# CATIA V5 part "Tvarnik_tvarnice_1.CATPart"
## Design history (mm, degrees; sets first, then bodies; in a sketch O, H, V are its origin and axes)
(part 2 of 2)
Body4 "Tvarnice"
  Sketch42 on face of Solid1, origin (1.6, 0, 0), H (0, 1, 0), V (0, 0, 1)
    line L1 (80, 80) -> (80, -80)
    line L2 (80, -80) -> (-80, -80)
    line L3 (-80, -80) -> (-80, 80)
    line L4 (-80, 80) -> (80, 80)
    length L4 = 160
    length L1 = 160
    vertical: L1 V, L3 V
    horizontal: L2 H, L4 H
    equidistance: L1 L3 O, L2 L4 O
  Pocket14: profile Sketch42, direction (-1, 0, 0), length 16
  Body5 "Vicko"
    Solid2: linked copy from another document
  Remove2: tool Body5
  Trim1: faces to keep start face of Pocket14, faces to remove start face of Pocket14 (x35)
  Sketch43 on start face of Pocket14, origin (1.6, 0, 0), H (0, 1, 0), V (0, 0, 1)
    projected circle E1 centre (26.45, -66.45) radius 5.1 from start face of Pocket14
    projected circle E2 centre (-26.2, -66.08) radius 5.1 from start face of Pocket14
    projected circle E3 centre (-68.2522, 13.0002) radius 5.1 from start face of Pocket14
    projected circle E4 centre (-35.5625, 59.6882) radius 5.1 from start face of Pocket14
    projected circle E5 centre (38.2049, 58.0324) radius 5.1 from start face of Pocket14
    projected circle E6 centre (70.2785, -7.2128) radius 5.1 from start face of Pocket14
  Pad6: profile Sketch43, direction (-1, 0, 0), length 3
  Sketch44 on end face of Pad6, origin (-1.4, 0, 0), H (0, 1, 0), V (0, 0, 1)
    projected circle E1 centre (70.2785, -7.2128) radius 3 from end face of Pad6
    projected circle E2 centre (38.2049, 58.0324) radius 3 from end face of Pad6
    projected circle E4 centre (-68.2522, 13.0002) radius 3 from edge [face of Solid2 | end face of Pad6]
    projected circle E5 centre (-26.2, -66.08) radius 3 from end face of Pad6
    projected circle E6 centre (26.45, -66.45) radius 3 from end face of Pad6
  Pad7: profile Sketch44, direction (-1, 0, 0), length 0.3
  Sketch45 on start face of Pocket14, origin (1.6, 0, 0), H (0, 1, 0), V (0, 0, 1)
    projected arc E1 centre (-39.7026, -63.67) radius 8 from (-33.5229, -68.7505) to (-31.75, -64.54) ccw from edge [face of Solid1 | face of Solid1]
    projected arc E3 centre (-38.7, -63.15) radius 7 from (-37.0577, -56.3454) to (-42.5892, -57.3299) ccw from edge [face of Solid1 | face of Solid1]
    projected arc E4 centre (-42.6448, -57.2467) radius 0.1 from (-42.6019, -57.337) to (-42.5892, -57.3299) ccw from edge [face of Solid1 | face of Solid1]
    projected line E5 (-42.9183, -57.4874) -> (-42.6019, -57.337) from edge [face of Solid1 | face of Solid1]
    projected arc E6 centre (-43.1328, -57.0357) radius 0.5 from (-43.5459, -57.3175) to (-42.9183, -57.4874) ccw from edge [face of Solid1 | face of Solid1]
    projected line E7 (-44.5334, -55.87) -> (-43.5459, -57.3175) from edge [face of Solid1 | face of Solid1]
    projected arc E8 centre (-44.9464, -56.1518) radius 0.5 from (-44.5334, -55.87) to (-44.634, -55.7614) ccw from edge [face of Solid1 | face of Solid1]
    projected arc E9 centre (0, 0) radius 71.425 from (-64.1739, -31.3568) to (-44.634, -55.7614) ccw from edge [face of Solid1 | face of Solid1]
    projected arc E10 centre (0, 0) radius 71.425 from (-71.1311, 6.4726) to (-64.1739, -31.3568) ccw from edge [face of Solid1 | face of Solid1]
    projected arc E11 centre (-73.1229, 6.6538) radius 2 from (-71.1311, 6.4726) to (-71.9052, 8.2404) ccw from edge [face of Solid1 | face of Solid1]
    projected arc E12 centre (-68.2522, 13.0002) radius 6 from (-69.8997, 18.7696) to (-71.9052, 8.2404) ccw from edge [face of Solid1 | face of Solid1]
    projected arc E13 centre (-70.4489, 20.6927) radius 2 from (-69.8997, 18.7696) to (-68.5299, 20.1291) ccw from edge [face of Solid1 | face of Solid1]
    projected arc E14 centre (0, 0) radius 71.425 from (-42.3563, 57.5107) to (-68.5299, 20.1291) ccw from edge [face of Solid1 | face of Solid1]
    projected arc E15 centre (-43.5423, 59.121) radius 2 from (-42.3563, 57.5107) to (-41.5474, 59.2628) ccw from edge [face of Solid1 | face of Solid1]
    projected arc E16 centre (-35.5625, 59.6882) radius 6 from (-32.3394, 64.749) to (-41.5474, 59.2628) ccw from edge [face of Solid1 | face of Solid1]
    projected arc E17 centre (-31.265, 66.4359) radius 2 from (-32.3394, 64.749) to (-30.8799, 64.4733) ccw from edge [face of Solid1 | face of Solid1]
    projected arc E18 centre (-31.265, 66.4359) radius 2 from (-30.8799, 64.4733) to (-30.4134, 64.6263) ccw from edge [face of Solid1 | face of Solid1]
    projected arc E19 centre (0, 0) radius 71.425 from (33.2826, 63.1965) to (-30.4134, 64.6263) ccw from edge [face of Solid1 | face of Solid1]
    projected arc E20 centre (34.2145, 64.9661) radius 2 from (33.2826, 63.1965) to (34.4133, 62.976) ccw from edge [face of Solid1 | face of Solid1]
    projected arc E21 centre (34.2145, 64.9661) radius 2 from (34.4133, 62.976) to (35.2121, 63.2327) ccw from edge [face of Solid1 | face of Solid1]
    projected arc E22 centre (38.2049, 58.0324) radius 6 from (44.1647, 57.3389) to (35.2121, 63.2327) ccw from edge [face of Solid1 | face of Solid1]
    projected arc E23 centre (46.1513, 57.1077) radius 2 from (44.1647, 57.3389) to (44.1679, 56.8506) ccw from edge [face of Solid1 | face of Solid1]
    projected arc E24 centre (46.1513, 57.1077) radius 2 from (44.1679, 56.8506) to (44.8942, 55.5522) ccw from edge [face of Solid1 | face of Solid1]
    projected arc E25 centre (0, 0) radius 71.425 from (68.6438, 19.7372) to (44.8942, 55.5522) ccw from edge [face of Solid1 | face of Solid1]
    projected arc E26 centre (68.5477, 19.7095) radius 0.1 from (68.6445, 19.7346) to (68.6438, 19.7372) ccw from edge [face of Solid1 | face of Solid1]
    projected arc E27 centre (68.5476, 19.7096) radius 0.1001 from (68.6357, 19.662) to (68.6445, 19.7346) ccw from edge [face of Solid1 | face of Solid1]
    projected arc E28 centre (68.5477, 19.7095) radius 0.1 from (68.6344, 19.6597) to (68.6357, 19.662) ccw from edge [face of Solid1 | face of Solid1]
    projected line E29 (65.7164, 14.5806) -> (68.6344, 19.6597) from edge [face of Solid1 | face of Solid1]
    projected arc E30 centre (69.5316, 12.3887) radius 4.4 from (65.7164, 14.5806) to (70.8571, 8.1931) ccw from edge [face of Solid1 | face of Solid1]
    projected arc E31 centre (70.8872, 8.0978) radius 0.1 from (70.9819, 8.13) to (70.8571, 8.1931) ccw from edge [face of Solid1 | face of Solid1]
    projected arc E33 centre (69.7785, -6.9628) radius 6 from (72.2645, -12.4235) to (75.4588, -5.0305) ccw from edge [face of Solid1 | face of Solid1]
    projected line E34 (70.9819, 8.13) -> (75.4588, -5.0305) from edge [face of Solid1 | face of Solid1]
    projected arc E35 centre (72.4717, -12.8786) radius 0.5 from (72.2645, -12.4235) to (72.1405, -12.504) ccw from edge [face of Solid1 | face of Solid1]
    projected line E36 (72.1405, -12.504) -> (72.0071, -12.6219) from edge [face of Solid1 | face of Solid1]
    projected line E37 (71.6567, -12.9317) -> (72.0071, -12.6219) from edge [face of Solid1 | face of Solid1]
    projected line E38 (70.1987, -14.2207) -> (71.6567, -12.9317) from edge [face of Solid1 | face of Solid1]
    projected arc E39 centre (70.861, -14.9699) radius 1 from (70.1987, -14.2207) to (69.8826, -14.7632) ccw from edge [face of Solid1 | face of Solid1]
    projected arc E40 centre (0, 0) radius 71.425 from (34.7, -62.4295) to (69.8826, -14.7632) ccw from edge [face of Solid1 | face of Solid1]
    projected line E41 (34.7, -63.3874) -> (34.7, -62.4295) from edge [face of Solid1 | face of Solid1]
    projected line E42 (34.7, -63.3874) -> (34.6998, -63.4087) from edge [face of Solid1 | face of Solid1]
    projected arc E43 centre (34.5768, -63.4037) radius 0.123 from (34.6907, -63.4503) to (34.6998, -63.4087) ccw from edge [face of Solid1 | face of Solid1]
    projected arc E45 centre (39.6, -65.7) radius 5.4 from (34.6823, -63.4692) to (34.2, -65.7) ccw from edge [face of Solid1 | face of Solid1]
    projected line E46 (34.6907, -63.4503) -> (34.6823, -63.4692) from edge [face of Solid1 | face of Solid1]
    projected arc E47 centre (27.2, -65.7) radius 7 from (29.0596, -72.4485) to (34.2, -65.7) ccw from edge [face of Solid1 | face of Solid1]
    projected line E48 (27.2179, -73.1928) -> (29.0487, -72.4522) from edge [face of Solid1 | face of Solid1]
    projected line E49 (27.2179, -73.1928) -> (27.1999, -73.1995) from edge [face of Solid1 | face of Solid1]
    projected line E50 (27.1999, -73.1995) -> (27.1807, -73.2) from edge [face of Solid1 | face of Solid1]
    projected line E51 (26.95, -73.2) -> (27.1807, -73.2) from edge [face of Solid1 | face of Solid1]
    projected arc E52 centre (26.95, -65.95) radius 7.25 from (19.7, -65.95) to (26.95, -73.2) ccw from edge [face of Solid1 | face of Solid1]
    projected line E53 (19.7, -54.5084) -> (19.7, -65.95) from edge [face of Solid1 | face of Solid1]
    projected arc E54 centre (10.55, -54.5084) radius 9.15 from (19.7, -54.5084) to (14.5407, -46.2746) ccw from edge [face of Solid1 | face of Solid1]
    projected arc E55 centre (10.55, -54.5084) radius 9.15 from (14.5407, -46.2746) to (12.2, -45.5084) ccw from edge [face of Solid1 | face of Solid1]
    projected arc E56 centre (-1.5593, -117.2) radius 73 from (12.028, -45.4756) to (8.5876, -44.9086) ccw from edge [face of Solid1 | face of Solid1]
    projected arc E57 centre (-1.5593, -117.2) radius 73 from (12.2, -45.5084) to (12.028, -45.4756) ccw from edge [face of Solid1 | face of Solid1]
    projected arc E58 centre (-1.5593, -117.2) radius 73 from (8.5876, -44.9086) to (-13.7, -45.2166) ccw from edge [face of Solid1 | face of Solid1]
    projected arc E59 centre (-12.6167, -52.2166) radius 7.0833 from (-13.7, -45.2166) to (-14.8563, -45.4967) ccw from edge [face of Solid1 | face of Solid1]
    projected arc E60 centre (-12.6167, -52.2166) radius 7.0833 from (-14.8563, -45.4967) to (-19.7, -52.2166) ccw from edge [face of Solid1 | face of Solid1]
    projected line E61 (-19.7, -52.2166) -> (-19.7, -67.2) from edge [face of Solid1 | face of Solid1]
    projected arc E62 centre (-25.7, -67.2) radius 6 from (-25.7, -73.2) to (-19.7, -67.2) ccw from edge [face of Solid1 | face of Solid1]
    projected line E63 (-25.7, -73.2) -> (-25.725, -73.1988) from edge [face of Solid1 | face of Solid1]
    projected line E64 (-25.7279, -73.1975) -> (-25.7474, -73.1876) from edge [face of Solid1 | face of Solid1]
    point P123 (-25.7279, -73.1975)
    projected line E65 (-25.7474, -73.1876) -> (-28.2581, -71.7985) from edge [face of Solid1 | face of Solid1]
    projected line E66 (-33.494, -68.9015) -> (-28.2581, -71.7985) from edge [face of Solid1 | face of Solid1]
    projected arc E67 centre (-33.4456, -68.814) radius 0.1 from (-33.5229, -68.7505) to (-33.494, -68.9015) ccw from edge [face of Solid1 | face of Solid1]
    line L1 (29.0487, -72.4522) -> (29.0596, -72.4485)
    line L2 (-25.7279, -73.1975) -> (-25.725, -73.1988)
    point P131 (-25.7279, -73.1975)
    coincidence: P131 E64, P123 P131
  Pad8: profile Sketch45, direction (-1, 0, 0), length 0.3
  Sketch46 on end face of Pocket14, origin (-14.4, 0, 0), H (0, -1, 0), V (0, 0, 1)
    line L1 (90, 90) -> (90, -90)
    line L2 (90, -90) -> (-90, -90)
    line L3 (-90, -90) -> (-90, 90)
    line L4 (-90, 90) -> (90, 90)
    length L4 = 180
    length L1 = 180
    vertical: L1 V, L3 V
    horizontal: L2 H, L4 H
    equidistance: L1 L3 O, L2 L4 O
  Pocket15: profile Sketch46, direction (-1, 0, 0), length 30
  DatumCurve31 to DatumCurve33
  Plane3: stored without definition
  Plane4: stored without definition
  Sketch47 on xy-plane, origin (0, 0, 0), H (1, 0, 0), V (0, 1, 0)
    line L1 (-5.1, 0) -> (-5.1, 1)
    arc A1 centre (-8.8103, -0.4945) radius 4 from (-5.1, 1) to (-8.6, 3.5) ccw
    line L2 (-8.6, 3.5) -> (-8.6, 0)
    line L3 (-8.6, 0) -> (-5.1, 0)
    distance L3 H = 0
    length L1 = 1
    length L2 = 3.5
    distance L1 V = 5.1
    distance L2 V = 8.6
    radius A1 = 4
    vertical: L1 V, L2 V
    horizontal: L3 H
  Shaft1: profile Sketch47, axis Sketch47.L3, angle 360
  DatumCurve34
  DatumCurve35
  Sketch48 on end face of Pocket15, origin (-44.4, 0, 0), H (0, -1, 0), V (0, 0, 1)
    projected arc E1 centre (0, 0) radius 18.5 from (18.5, 0) to (-18.5, 0) ccw from edge of DatumCurve34
    projected arc E2 centre (0, 0) radius 18.5 from (-18.5, 0) to (18.5, 0) ccw from edge of DatumCurve35
  Pad9: profile Sketch48, direction (1, 0, 0), length 29
  DatumCurve36
  DatumCurve37
  DatumSurface32
  Sketch49 on end face of Pad9, origin (-15.4, 0, 0), H (0, -1, 0), V (0, 0, 1)
    projected arc E1 centre (0, 0) radius 8.5 from (8.5, 0) to (-8.5, 0) ccw from edge of DatumCurve36
    projected arc E2 centre (0, 0) radius 8.5 from (-8.5, 0) to (8.5, 0) ccw from edge of DatumCurve37
  Pad10: profile Sketch49, direction (1, 0, 0), length 6.8
  Sketch50 on face of Solid1, origin (-2.9, 0, 0), H (0, -1, 0), V (0, 0, 1)
    projected circle E1 centre (10, 25) radius 3.5 from edge [end face of Pad4 | face of Pocket7 from Sketch12.E8]
  Sketch51 on face of Pocket15 from Sketch46.L4, origin (0, 0, 90), H (1, 0, 0), V (0, 1, 0)
    circle A1 centre (-30.4, 65) radius 5
    point P1 (-30.4, 65)
    circle A2 centre (-30.4, 33) radius 5
    point P2 (-30.4, 33)
    circle A3 centre (-30.4, -33) radius 5
    point P3 (-30.4, -33)
    circle A4 centre (-30.4, -65) radius 5
    point P4 (-30.4, -65)
    construction line L1 (-14.4, -85) -> (-44.4, -85)
    construction line L2 (-14.4, 85) -> (-44.4, 85)
    radius A4 = 5
    radius A3 = 5
    radius A2 = 5
    radius A1 = 5
    distance P4 L1 = 20
    distance P3 P4 = 32
    distance L2 P1 = 20
    distance P2 P1 = 32
  Pad11: profile Sketch51, direction (0, 0, -1), up to the existing solid (limit type 2)
  Sketch52 on face of Pad4 from Sketch9.L4, origin (0, 0, 90), H (1, 0, 0), V (0, 1, 0)
    circle A1 centre (34.9443, -53.3819) radius 5
    circle A2 centre (34.9443, 5.4608) radius 5
    circle A3 centre (34.9443, 54.6938) radius 5
    circle A4 centre (34.9443, 77.599) radius 5
    point P4 (34.9443, 77.599)
    reference projected line E1 (47.6, 90) -> (47.6, -90) from edge [face of Pad4 from Sketch9.L4 | end face of Pad4]
    radius A4 = 5
    radius A3 = 5
    radius A2 = 5
    radius A1 = 5
    distance P4 E1 = 12.6557
  Body6 "MANIFOLD_SOLID_BREP #135"
    Solid3: solid without history
  Remove3: tool Body6
  Sketch53 on face of Solid2, origin (0, 11.5, 0), H (-1, 0, 0), V (0, 0, 1)
  Pad12: profile Sketch53, direction (0, -1, 0), up to face of Solid2
  Sketch54 on face of Solid2, origin (0, -11.5, 0), H (1, 0, 0), V (0, 0, 1)
    projected line E1 (-2.8, -44.0344) -> (-0.8933, -43.906) from edge [face of Solid2 | face of Solid2]
    point P1 (-2.8, -44.0344)
    projected arc E2 centre (-0.9006, -43.8056) radius 0.1006 from (-0.8933, -43.906) to (-0.8, -43.8052) ccw from edge [face of Solid2 | face of Solid2]
    projected line E3 (-0.8, -43.8052) -> (-0.8, -44.1794) from edge [face of Solid2 | face of Pad12]
    projected arc E4 centre (-0.9007, -44.1803) radius 0.1007 from (-0.8933, -44.2807) to (-0.8, -44.1794) ccw from edge [face of Solid2 | face of Pad12]
    projected line E5 (-0.8933, -44.2807) -> (-0.4, -44.2807) from edge [face of Solid2 | face of Pad12]
    projected line E6 (-0.4, -44.8326) -> (-0.4, -44.2807) from edge [face of Solid2 | face of Solid2]
    projected line E7 (-0.4, -44.8326) -> (-2.8, -44.7051) from edge [face of Solid2 | face of Solid2]
    line L1 (-2.8, -44.0344) -> (-3.0461, -44.0509)
    point P15 (-2.8, -44.0344)
    line L2 (-2.8, -44.7051) -> (-3.0461, -44.692)
    point P17 (-3.0461, -44.692)
    line L3 (-3.0461, -44.692) -> (-3.0461, -44.0509)
    point P18 (-3.0461, -44.692)
    length L3 = 0.6411
    distance P15 P1 = 0
    distance P17 P18 = 0
    coincidence: P15 E1, P18 L2
    tangency: L1 E2
    parallelism: L2 E7
    vertical: L3 V
  Sketch55 on start face of Pocket14, origin (1.6, 0, 0), H (0, 1, 0), V (0, 0, 1)
    projected arc E1 centre (-1.3665, -117.1471) radius 73.0211 from (-11, -44.7643) to (-11.5, -44.8326) ccw from edge [face of Solid2 | face of Solid2]
  Rib1: profile Sketch54, centre curve Sketch55
  Sketch56 on face of Solid3, origin (0, -11, 0), H (-1, 0, 0), V (0, 0, 1)
    line L1 (0.7047, -44.3237) -> (1.0185, -44.3237)
    line L2 (1.0185, -44.3237) -> (1.0185, -44.065)
    line L3 (1.0185, -44.065) -> (0.7047, -44.065)
    line L4 (0.7047, -44.065) -> (0.7047, -44.3237)
    horizontal: L1 H, L3 H
    vertical: L2 V, L4 V
  Pad13: profile Sketch56, direction (0, -1, 0), length 1
  Sketch57 on face of Solid3, origin (0, 12, 0), H (1, 0, 0), V (0, 0, 1)
    projected line E1 (-2.9, -44.5067) -> (-2.8052, -44.5003) from edge [face of Solid2 | face of Solid3]
    projected line E2 (-2.8052, -44.5003) -> (-0.8933, -44.3707) from edge [face of Solid2 | face of Solid3]
    line L1 (-2.9, -44.5067) -> (-2.9, -44.3067)
    line L2 (-2.9, -44.3067) -> (-0.8933, -44.3707)
    length L1 = 0.2
    vertical: L1 V
  Sketch58 on face of Pad12, origin (-0.8, 0, 0), H (0, 1, 0), V (0, 0, 1)
    projected arc E1 centre (-1.1745, -116.1657) radius 72.9938 from (2.4737, -43.2632) to (-1.0654, -43.172) ccw from edge [face of Solid3 | face of Pad12]
    projected arc E2 centre (-1.1745, -116.1657) radius 72.9938 from (10.9113, -44.1794) to (6.5, -43.5765) ccw from edge [face of Solid3 | face of Pad12]
    projected line E3 (11.4217, -44.267) -> (10.9113, -44.1794) from edge [face of Pad12 | face of Solid3]
    projected arc E4 centre (-0.6882, -116.2646) radius 73.0936 from (-6.5, -43.4025) to (-10.994, -43.9012) ccw from edge [face of Pad12 | face of Solid3]
    point P7 (-6.5, -43.4025)
    arc A1 centre (-0.6882, -116.2646) radius 73.0936 from (-6.5, -43.4025) to (-1.0654, -43.172) cw
    point P10 (-6.5, -43.4025)
    point P11 (-3.695, -43.2329)
    arc A2 centre (-1.1745, -116.1657) radius 72.9938 from (2.4737, -43.2632) to (6.5, -43.5765) cw
    point P13 (5.4808, -43.476)
    arc A3 centre (4.3044, -85.7576) radius 42.0967 from (11.4217, -44.267) to (12.116, -44.3921) cw
    point P15 (12.116, -44.3921)
    coincidence: P10 E4, A1 P11, P11 E4, A2 P13, P13 E2, P15 E2, P7 P10
    tangency: A3 E3
  Slot1: profile Sketch57, centre curve Sketch58
  DatumSurface33
  Sketch59 on face of Pad12, origin (-0.8, 0, 0), H (0, 1, 0), V (0, 0, 1)
    projected arc E1 centre (-1.1745, -116.1657) radius 72.9938 from (2.4737, -43.2632) to (-1.0654, -43.172) ccw from edge [face of Solid3 | face of Pad12]
    projected arc E2 centre (-0.6882, -116.2646) radius 73.0936 from (-1.0654, -43.172) to (-1.9017, -43.1811) ccw from edge [face of Pad12 | face of Solid3]
    projected arc E3 centre (-0.6882, -116.2646) radius 73.0936 from (-1.9017, -43.1811) to (-2, -43.1828) ccw from edge [face of Pad12 | face of Solid3]
    projected arc E4 centre (-0.6882, -116.2646) radius 73.0936 from (-6.5, -43.4025) to (-10.994, -43.9012) ccw from edge [face of Pad12 | face of Solid3]
    projected arc E5 centre (-1.1745, -116.1657) radius 72.9938 from (10.9113, -44.1794) to (6.5, -43.5765) ccw from edge [face of Solid3 | face of Pad12]
    arc A1 centre (-0.6882, -116.2646) radius 73.0936 from (-10.994, -43.9012) to (-11.5363, -43.9806) ccw
    point P12 (-11.5363, -43.9806)
    point P13 (-11.4271, -43.9642)
    arc A2 centre (-0.6882, -116.2646) radius 73.0936 from (-6.5, -43.4025) to (-2, -43.1828) cw
    point P15 (-6.5, -43.4025)
    point P16 (-2.4662, -43.1927)
    arc A3 centre (-1.1745, -116.1657) radius 72.9938 from (6.5, -43.5765) to (2.4737, -43.2632) ccw
    point P18 (4.2149, -43.3712)
    arc A4 centre (-1.1745, -116.1657) radius 72.9938 from (10.9113, -44.1794) to (12.2372, -44.4146) cw
    point P20 (12.2372, -44.4146)
    point P21 (12.1539, -44.3991)
    coincidence: P12 E4, A1 P13, P13 E4, P15 E4, A2 P16, P16 E3, A3 P18, P18 E5, P20 E5, A4 P21, P21 E5
  Sketch60 on face of Rib1, origin (0, -10.6901, 0.0739), H (1, 0, 0), V (0, 0.0069, 1)
    projected arc E1 centre (-0.9006, -43.8123) radius 0.1006 from (-0.8933, -43.9126) to (-0.8, -43.8118) ccw from edge [face of Rib1 | face of Rib1]
    projected line E2 (-0.8, -43.9762) -> (-0.8, -43.8118) from edge [face of Pad12 | face of Rib1]
    point P3 (-0.8, -43.9762)
    projected line E3 (-2.9, -44.0773) -> (-0.8, -43.9762) from edge [face of Solid3 | face of Rib1]
    point P6 (-0.8, -43.9762)
    projected line E4 (-2.8052, -44.099) -> (-1.1087, -43.9903) from edge [face of Slot1 | face of Slot1]
    projected line E5 (-2.9, -44.0723) -> (-2.9, -44.1051) from edge [face of Slot1 | face of Slot1]
    projected line E6 (-2.9, -44.0773) -> (-2.9, -44.0477) from edge [face of Rib1 | face of Slot1]
    projected line E7 (-2.9, -44.0723) -> (-2.9, -44.0477) from edge [face of Rib1 | face of Slot1]
    point P12 (-2.9, -44.0477)
    projected line E8 (-2.8, -44.041) -> (-2.9, -44.0477) from edge [face of Rib1 | face of Rib1]
    point P14 (-2.9, -44.0477)
    projected line E9 (-1.8374, -43.9762) -> (-2.8, -44.041) from edge [face of Rib1 | face of Rib1]
    projected line E10 (-0.8933, -43.9126) -> (-1.5388, -43.9561) from edge [face of Rib1 | face of Rib1]
    line L1 (-1.8374, -43.9762) -> (-1.5388, -43.9561)
    line L2 (-2.9, -44.1051) -> (-2.9, -44.1366)
    line L3 (-2.9, -44.1366) -> (-0.8, -43.9762)
    point P20 (-0.8, -43.9762)
    length L2 = 0.0315
    tangency: L1 E1
    coincidence: P3 P6, P12 P14, P20 E2
    vertical: L2 V
  Sketch61 on face of Pad12, origin (-0.8, 0, 0), H (0, 1, 0), V (0, 0, 1)
    projected arc E1 centre (-0.6882, -116.2646) radius 73.0936 from (-6.5, -43.4025) to (-10.994, -43.9012) ccw from edge [face of Pad12 | face of Solid3]
    point P1 (-6.5, -43.4025)
    line L1 (-10.994, -43.9012) -> (-11.0912, -43.9151)
    arc A1 centre (-1.1195, -116.3252) radius 73.094 from (-10.994, -43.9012) to (-6.5, -43.4295) cw
    point P5 (-6.5, -43.4295)
    arc A2 centre (-1.2519, -114.5313) radius 71.2952 from (-6.5, -43.4295) to (-2.5, -43.247) cw
    point P7 (-2.5, -43.247)
    reference projected point E2 (-2.5, -43.184) from vertex [face of Solid2 | face of Solid3 | face of Pad12]
    reference projected line E3 (-2.5, -42) -> (-2.5, -43.0842) from edge [face of Solid2 | face of Pad12]
    arc A3 centre (-1.198, -117.6157) radius 74.3801 from (-2.5, -43.247) to (2.5, -43.3276) cw
    point P9 (2.5, -43.3276)
    reference projected line E4 (2.5, -42) -> (2.5, -43.1646) from edge [face of Pad12 | face of Solid2]
    reference projected line E5 (2.5, -43.2645) -> (2.4737, -43.2632) from edge [face of Pad12 | face of Solid3]
    arc A4 centre (-1.182, -116.1599) radius 72.9253 from (2.5, -43.3276) to (11.5, -44.3457) cw
    point P11 (11.5, -44.3457)
    reference projected point E6 (11.5, -44.2807) from vertex [face of Solid3 | face of Pad12 | face of Slot1 | face of Solid2]
    radius A1 = 73.094
    distance P1 P5 H = 0
    distance P5 P1 = 0.027
    distance E2 P7 = 0.063
    distance P7 E3 = 0
    distance P9 E4 = 0
    distance E5 P9 = 0.063
    distance E6 P11 V = 0.065
    distance P11 E6 H = 0
    tangency: L1 E1, A2 A1, A3 A2, A4 A2
  Rib2: profile Sketch60, centre curve Sketch61
  Curve1: Elements (vertex [face of Solid3 | face of Rib2 | face of Slot1]; vertex [face of Slot1 | face of Rib2 | face of Rib2]; vertex [face of Solid3 | face of Rib2])
  Curve2: Elements (vertex of Curve1; vertex [face of Solid3 | face of Solid3 | face of Rib2])
  DatumCurve38 to DatumCurve40
  DatumSurface34
  Sketch62 on start face of Pocket14, origin (1.6, 0, 0), H (0, 1, 0), V (0, 0, 1)
    projected line E1 (12, -44.7901) -> (12, -49.5) from edge of DatumCurve38
    projected line E2 (12, -45.3598) -> (12, -49.5) from edge of DatumCurve38
    projected line E3 (-11, -44.2758) -> (-11, -49.5) from edge of DatumCurve39
    projected line E4 (-11, -44.7643) -> (-11, -49.5) from edge of DatumCurve39
    projected arc E5 centre (-1.3665, -117.1471) radius 73.0211 from (-6.1, -44.2797) to (-10.9, -44.7511) ccw from edge [face of Solid2 | face of Solid3]
    projected arc E6 centre (-1.3665, -117.1471) radius 73.0211 from (-6, -44.2732) to (-6.1, -44.2797) ccw from edge [face of Solid3 | face of Solid2]
    projected arc E7 centre (-1.3665, -117.1471) radius 73.0211 from (-2, -44.1288) to (-6, -44.2732) ccw from edge [face of Solid3 | face of Solid2]
    projected arc E8 centre (-1.3665, -117.1471) radius 73.0211 from (2.9, -44.2508) to (-1.9, -44.128) ccw from edge [face of Solid2 | face of Solid3]
    projected arc E9 centre (-1.3665, -117.1471) radius 73.0211 from (-1.9, -44.128) to (-2, -44.1288) ccw from edge [face of Solid2 | face of Solid3]
    projected arc E10 centre (-1.3665, -117.1471) radius 73.0211 from (3, -44.2567) to (2.9, -44.2508) ccw from edge [face of Solid3 | face of Solid2]
    projected arc E11 centre (-1.3665, -117.1471) radius 73.0211 from (7, -44.6069) to (3, -44.2567) ccw from edge [face of Solid3 | face of Solid2]
    projected arc E12 centre (-1.3665, -117.1471) radius 73.0211 from (7.1, -44.6185) to (7, -44.6069) ccw from edge [face of Solid2 | face of Solid3]
    projected arc E13 centre (-1.3665, -117.1471) radius 73.021 from (11.9, -45.3413) to (7.1, -44.6185) ccw from edge [face of Solid2 | face of Solid3]
    projected arc E14 centre (-1.3665, -117.1471) radius 73.0211 from (12, -45.3598) to (11.9, -45.3413) ccw from edge [face of Solid3 | face of Solid2]
    line L1 (-11, -49.5) -> (-11, -50)
    line L2 (-11, -50) -> (12, -50)
    point P26 (12, -50)
    line L3 (12, -50) -> (12, -49.5)
    reference projected line E15 (-15, -50.5) -> (16, -50.5) from edge of DatumCurve40
    line L4 (-11, -44.7643) -> (-10.9, -44.7511)
    point P27 (-11, -44.7643)
    distance L2 E15 = 0.5
    vertical: L1 V, L3 V
    coincidence: P26 E1, P27 E5, P27 E3
    horizontal: L2 H
  Pad14: profile Sketch62, direction (-1, 0, 0), up to face of DatumSurface34
  Fillet12: radius 0.5, on edge [face of Solid2 | face of Solid2]
  Sketch63 on start face of Pocket14, origin (1.6, 0, 0), H (0, 1, 0), V (0, 0, 1)
    line L1 (16.5, -50) -> (-15.5, -50)
    line L2 (-15.5, -50) -> (-15.5, -80)
    line L3 (-15.5, -80) -> (16.5, -80)
    line L4 (16.5, -80) -> (16.5, -50)
    reference projected line E1 (16, -80) -> (-15, -80) from edge [face of Solid3 | face of Pocket14 from Sketch42.L2]
    reference intersected line E2 (-15.5, -104.5) -> (-15.5, -80.366) from face of Solid3
    reference projected point E3 (16.5, -80) from edge [face of Pocket14 from Sketch42.L2 | face of Solid3]
    reference projected line E4 (16, -50) -> (-15, -50) from edge [face of Solid3 | face of Solid3]
    distance L3 E1 = 0
    distance L2 E2 = 0
    distance L4 E3 = 0
    distance L1 E4 = 0
    horizontal: L1 H, L3 H
    vertical: L2 V, L4 V
  Pad15: profile Sketch63, direction (-1, 0, 0), length 0.5
  Fillet13: radius 0.5, on edge [face of Pad15 | face of Pad15] (x2); edge [face of Solid3 | face of Solid3] (x2)
  Plane5: stored without definition
  Sketch64 on Plane5, origin (0, -3.2667, -0.0566), H (1, 0, 0), V (0, -0.0179, 0.9998)
    point P2 (-1.5388, -43.1773)
    point P3 (-1.5388, -43.1773)
    point P4 (-1.871, -43.1995)
    arc A1 centre (-0.8998, -43.0346) radius 0.1 from (-0.8, -43.0279) to (-0.8931, -43.1343) cw
    point P6 (-0.8, -43.0279)
    point P7 (-0.8931, -43.1343)
    line L1 (-0.9925, -43.1409) -> (-0.8931, -43.1343)
    point P8 (-0.8931, -43.1343)
    line L2 (-0.8, -43.0279) -> (-1.8776, -43.0997)
    point P9 (-1.8776, -43.0997)
    line L3 (-1.8776, -43.0997) -> (-1.871, -43.1995)
    point P10 (-1.8776, -43.0997)
    point P11 (-1.871, -43.1995)
    line L4 (-0.9925, -43.1409) -> (-1.5388, -43.1773)
    line L5 (-1.5388, -43.1773) -> (-1.871, -43.1995)
    construction line L6 (-0.8, -43.0347) -> (-0.8, -44.3717)
    radius A1 = 0.1
    distance P7 P8 = 0
    distance L6 P6 = 0
    distance L2 L4 = 0.1
    distance L3 P6 = 1.08
    distance P11 P4 = 0
    distance P4 L3 = 0
    distance P9 P10 = 0
    distance P9 H = 43.0997
    distance P9 V = 1.8776
    distance P6 H = 43.0279
    distance P6 V = 0.8
    distance P3 P2 = 0
    tangency: A1 L5
    parallelism: L1 L4, L2 L5
    perpendicularity: L3 L5
  Sketch65 on face of Pad12, origin (-0.8, 0, 0), H (0, 1, 0), V (0, 0, 1)
  Slot2: profile Sketch64, centre curve Sketch65
  Chamfer5: length 5, angle 45, on edge [face of Pocket15 from Sketch46.L2 | face of Pocket15 from Sketch46.L3]; edge [face of Pocket14 from Sketch42.L2 | face of Pocket14 from Sketch42.L1]; edge [face of Pocket14 from Sketch42.L1 | face of Pocket14 from Sketch42.L4]; edge [face of Pocket15 from Sketch46.L3 | face of Pocket15 from Sketch46.L4]; edge [face of Pocket15 from Sketch46.L4 | face of Pocket15 from Sketch46.L1]; edge [face of Pocket14 from Sketch42.L4 | face of Pocket14 from Sketch42.L3]; edge [face of Pocket14 from Sketch42.L3 | face of Pocket14 from Sketch42.L2]; edge [face of Pocket15 from Sketch46.L1 | face of Pocket15 from Sketch46.L2]
  Sketch66 on face of Pad3 from Sketch7.L2, origin (0, 0, -80), H (1, 0, 0), V (0, -1, 0)
    circle A1 centre (8.6773, 54.4593) radius 4.8015
  Sketch67 on face of Pocket15 from Sketch46.L4, origin (0, 0, 90), H (1, 0, 0), V (0, 1, 0)
    circle A1 centre (-30.4, -65) radius 6
    circle A2 centre (-30.4, -33) radius 6
    circle A3 centre (-30.4, 33) radius 6
    circle A4 centre (-30.4, 65) radius 6
    reference projected line E1 (-14.4, -85) -> (-44.4, -85) from edge [face of Pocket15 from Sketch46.L4 | face of Chamfer5]
    reference projected line E2 (-44.4, -90) -> (-44.4, 90) from edge [face of Pocket15 from Sketch46.L4 | end face of Pocket15]
    reference projected line E3 (-14.4, 85) -> (-44.4, 85) from edge [face of Chamfer5 | face of Pocket15 from Sketch46.L4]
    radius A4 = 6
    radius A3 = 6
    radius A2 = 6
    radius A1 = 6
    distance A1 E1 = 26
    distance A1 E2 = 20
    distance A2 A1 = 20
    distance A2 E2 = 20
    distance A4 E3 = 26
    distance A4 E2 = 20
    distance A3 A4 = 20
    distance A3 E2 = 20
  Pad16: profile Sketch67, direction (0, 0, -1), length 1
  Mirror2: of Pad16, about xy-plane
  Fillet14: radius 0.5, on edge [face of Solid3 | face of Pad15]
  Fillet15: radius 0.5, on edge [face of Solid2 | face of Solid2]
  Sketch68 on face of Solid2, origin (-0.8, 0, 0), H (0, 1, 0), V (0, 0, 1)
    projected circle E2 centre (0, 0) radius 1 from face of Solid2
    projected arc E4 centre (-30.5215, -3.9253) radius 2 from (-30.5215, -1.9253) to (-32.5215, -3.9253) ccw from edge [face of Solid2 | face of Solid2]
    projected line E5 (-32.5215, -3.9253) -> (-32.5215, -19.9253) from edge [face of Solid2 | face of Solid2]
    projected line E6 (-24.6215, -1.9253) -> (-30.5215, -1.9253) from edge [face of Solid2 | face of Solid2]
    projected line E7 (-24.6215, 3.3747) -> (-24.6215, -1.9253) from edge [face of Solid2 | face of Solid2]
    projected arc E8 centre (-22.6215, 3.3747) radius 2 from (-22.6215, 5.3747) to (-24.6215, 3.3747) ccw from edge [face of Solid2 | face of Solid2]
    projected line E9 (2.3785, 5.3747) -> (-22.6215, 5.3747) from edge [face of Solid2 | face of Solid2]
    projected arc E10 centre (2.3785, 3.3747) radius 2 from (4.3785, 3.3747) to (2.3785, 5.3747) ccw from edge [face of Solid2 | face of Solid2]
    projected line E11 (4.3785, -1.9253) -> (4.3785, 3.3747) from edge [face of Solid2 | face of Solid2]
    projected line E12 (10.2785, -1.9253) -> (4.3785, -1.9253) from edge [face of Solid2 | face of Solid2]
    projected arc E13 centre (10.2785, -3.9253) radius 2 from (12.2785, -3.9253) to (10.2785, -1.9253) ccw from edge [face of Solid2 | face of Solid2]
    projected line E14 (12.2785, -19.9253) -> (12.2785, -3.9253) from edge [face of Solid2 | face of Solid2]
    projected arc E15 centre (10.2785, -19.9253) radius 2 from (10.2785, -21.9253) to (12.2785, -19.9253) ccw from edge [face of Solid2 | face of Solid2]
    projected line E16 (-30.5215, -21.9253) -> (10.2785, -21.9253) from edge [face of Solid2 | face of Solid2]
    projected arc E17 centre (-30.5215, -19.9253) radius 2 from (-32.5215, -19.9253) to (-30.5215, -21.9253) ccw from edge [face of Solid2 | face of Solid2]
    projected arc E18 centre (-22.6215, 10.8747) radius 2 from (-24.6215, 10.8747) to (-22.6215, 8.8747) ccw from edge [face of Solid2 | face of Solid2]
    projected line E19 (-24.6215, 16.1747) -> (-24.6215, 10.8747) from edge [face of Solid2 | face of Solid2]
    projected line E20 (-30.5215, 16.1747) -> (-24.6215, 16.1747) from edge [face of Solid2 | face of Solid2]
    projected arc E21 centre (-30.5215, 18.1747) radius 2 from (-32.5215, 18.1747) to (-30.5215, 16.1747) ccw from edge [face of Solid2 | face of Solid2]
    projected line E22 (-32.5215, 34.1747) -> (-32.5215, 18.1747) from edge [face of Solid2 | face of Solid2]
    projected arc E23 centre (-30.5215, 34.1747) radius 2 from (-30.5215, 36.1747) to (-32.5215, 34.1747) ccw from edge [face of Solid2 | face of Solid2]
    projected line E24 (10.2785, 36.1747) -> (-30.5215, 36.1747) from edge [face of Solid2 | face of Solid2]
    projected arc E25 centre (10.2785, 34.1747) radius 2 from (12.2785, 34.1747) to (10.2785, 36.1747) ccw from edge [face of Solid2 | face of Solid2]
    projected line E26 (12.2785, 18.1747) -> (12.2785, 34.1747) from edge [face of Solid2 | face of Solid2]
    projected arc E27 centre (10.2785, 18.1747) radius 2 from (10.2785, 16.1747) to (12.2785, 18.1747) ccw from edge [face of Solid2 | face of Solid2]
    projected line E28 (4.3785, 16.1747) -> (10.2785, 16.1747) from edge [face of Solid2 | face of Solid2]
    projected line E29 (4.3785, 10.8747) -> (4.3785, 16.1747) from edge [face of Solid2 | face of Solid2]
    projected line E30 (-22.6215, 8.8747) -> (2.3785, 8.8747) from edge [face of Solid2 | face of Solid2]
    projected arc E31 centre (2.3785, 10.8747) radius 2 from (2.3785, 8.8747) to (4.3785, 10.8747) ccw from edge [face of Solid2 | face of Solid2]
  Pocket16: profile Sketch68, direction (-1, 0, 0), up to face of Solid2
  Chamfer6: length 0.5, second length 4.3, on edge [face of Solid2 | face of Pocket16] (x16)
  Fillet16: radius 1, on edge [face of Chamfer6 | face of Chamfer6] (x16)
  Fillet17: radius 1, on edge [face of Chamfer6 | face of Solid2]; edge [face of Solid2 | face of Chamfer6]; face of Solid2; face of Chamfer6
  DatumSurface35
  Sketch69 on face of Pad12, origin (-0.8, 0, 0), H (0, 1, 0), V (0, 0, 1)
    reference projected curve E1 from edge [face of Pad12 | face of Rib2]
    projected arc E2 centre (-1.1745, -116.1657) radius 73.0936 from (12.8553, -44.4313) to (11.5, -44.1794) ccw from edge [face of Solid2 | face of Pad12]
    projected arc E3 centre (-1.1745, -116.1657) radius 73.0936 from (12, -44.2693) to (11.5, -44.1794) ccw from edge [face of Solid2 | face of Pad12]
    line L1 (12, -44.2693) -> (12, -41.861)
    line L2 (12, -41.861) -> (-11, -41.861)
    line L3 (-11, -41.861) -> (-11, -43.7378)
    reference projected line E4 (-15.5, -50) -> (-11, -50) from edge [start face of Pocket14 | face of Pad15]
    line L4 (-10.9929, -43.7369) -> (-11, -43.7378)
    point P7 (-11, -43.7378)
    point P8 (12, -44.2693)
    point P9 (12, -44.2693)
    distance L2 E4 = 8.139
    length L1 = 2.4083
    length L3 = 1.8768
    vertical: L1 V, L3 V
    horizontal: L2 H
    coincidence: P7 E1, L1 P8, E2 P9, P8 P9
  Pocket17: profile Sketch69, direction (-1, 0, 0), up to face of DatumSurface35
